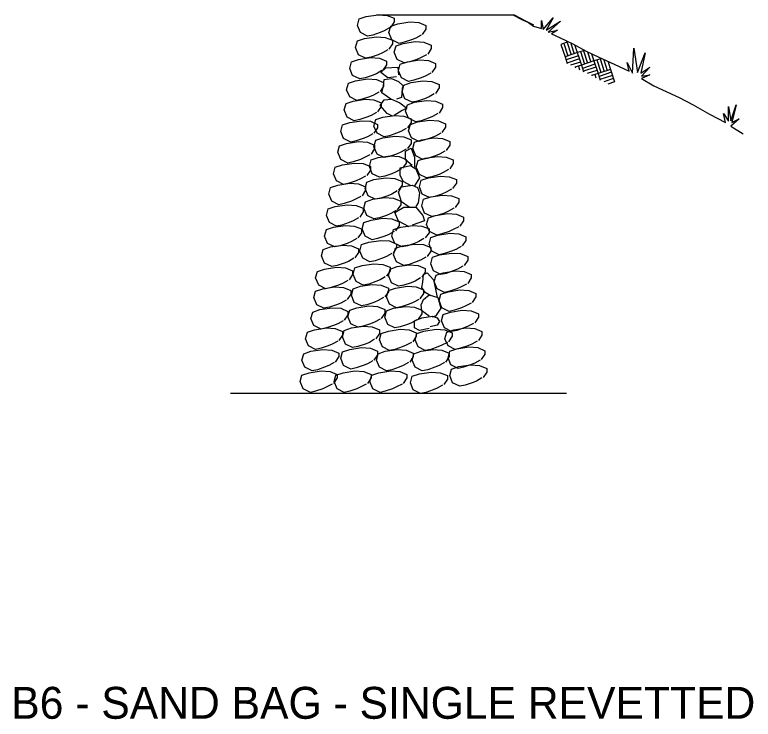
# Model space of a CAD drawing. Extents: x -0.04 to 2.79, y -0.02 to 1.81.
# Drawn here: x 0.1879 to 0.4291, y 0.9318 to 1.1619 of the extents above; entities that cross this region are included whole.
import ezdxf

# ---------------------------------------------------------------- set-up
doc = ezdxf.new("R2010")
doc.units = 0
doc.layers.add('Level 1', color=7, linetype='Continuous')

msp = doc.modelspace()

# ---------------------------------------------------------------- linework, layer by layer
at = {"layer": 'Level 1'}
for p, q in [((0.30607, 1.16192), (0.35105, 1.16192)), ((0.36861, 1.15304), (0.36629, 1.15222)), ((0.36629, 1.15222), (0.36766, 1.14818)), ((0.36731, 1.15256), (0.36861, 1.14853)), ((0.36834, 1.1529), (0.36964, 1.14887)), ((0.36957, 1.15256), (0.37066, 1.14921)), ((0.37087, 1.15187), (0.37306, 1.14545)), ((0.37169, 1.14955), (0.36766, 1.14818)), ((0.37203, 1.14853), (0.368, 1.14716)), ((0.37401, 1.1503), (0.37169, 1.14955)), ((0.37271, 1.14989), (0.37401, 1.14579)), ((0.37374, 1.15017), (0.37504, 1.14613)), ((0.37497, 1.14982), (0.37606, 1.14647)), ((0.37627, 1.14914), (0.37709, 1.14682)), ((0.36766, 1.14818), (0.36834, 1.146)), ((0.37237, 1.1475), (0.36827, 1.14613)), ((0.37271, 1.14647), (0.3695, 1.14545)), ((0.37709, 1.14682), (0.37306, 1.14545)), ((0.37941, 1.14757), (0.37709, 1.14682)), ((0.37709, 1.14682), (0.37846, 1.14278)), ((0.37811, 1.14716), (0.37941, 1.14313)), ((0.37914, 1.1475), (0.38044, 1.1434)), ((0.38037, 1.14716), (0.38146, 1.14374)), ((0.38174, 1.14647), (0.38249, 1.14408)), ((0.37306, 1.14545), (0.37087, 1.14477)), ((0.37306, 1.14545), (0.37087, 1.14477)), ((0.37101, 1.14477), (0.37107, 1.14463)), ((0.37203, 1.14511), (0.37237, 1.14395)), ((0.37306, 1.14545), (0.37374, 1.14326)), ((0.37743, 1.14579), (0.3734, 1.14442)), ((0.37777, 1.14477), (0.37367, 1.14347)), ((0.37811, 1.14374), (0.3749, 1.14272)), ((0.38249, 1.14408), (0.37846, 1.14278)), ((0.38249, 1.14408), (0.38386, 1.14005)), ((0.37846, 1.14278), (0.37627, 1.14203)), ((0.37846, 1.14278), (0.37627, 1.14203)), ((0.37641, 1.1421), (0.37647, 1.14196)), ((0.37743, 1.14244), (0.37777, 1.14128)), ((0.37846, 1.14278), (0.37914, 1.1406)), ((0.38283, 1.14313), (0.3788, 1.14176)), ((0.38317, 1.1421), (0.37907, 1.14073)), ((0.38351, 1.14107), (0.3803, 1.13998)), ((0.38386, 1.14005), (0.38167, 1.1393)), ((0.25836, 1.03828), (0.36814, 1.03828))]:
    msp.add_line(p, q, dxfattribs=at)
for points in [[(0.31031, 1.15762), (0.3086, 1.15666), (0.30723, 1.15611), (0.30491, 1.15529), (0.30313, 1.15495), (0.30081, 1.15611), (0.29985, 1.15844), (0.3004, 1.16055), (0.30272, 1.16131), (0.30662, 1.16192), (0.30956, 1.16172), (0.31188, 1.16076), (0.31188, 1.1596), (0.31072, 1.15782)], [(0.35064, 1.16192), (0.35358, 1.16035), (0.3557, 1.15939), (0.3574, 1.15823), (0.35993, 1.15748), (0.35993, 1.16001), (0.36055, 1.15707), (0.36383, 1.16096), (0.36151, 1.15686), (0.36622, 1.1598), (0.36212, 1.15625), (0.3652, 1.15686), (0.36328, 1.1557), (0.36581, 1.15454), (0.37025, 1.15242), (0.37456, 1.15003), (0.37866, 1.14811), (0.38372, 1.14579), (0.38857, 1.14347), (0.38796, 1.14634), (0.38973, 1.14285), (0.39014, 1.15105), (0.39131, 1.14306), (0.39383, 1.14948), (0.39247, 1.14285), (0.39534, 1.14483), (0.39267, 1.14189), (0.39534, 1.14231), (0.39267, 1.14114), (0.39671, 1.13875), (0.40491, 1.13485), (0.40956, 1.13253), (0.41482, 1.12946), (0.42008, 1.12672), (0.41947, 1.12966), (0.42104, 1.12713), (0.42104, 1.13198), (0.42179, 1.12727), (0.42357, 1.13253), (0.4222, 1.12672), (0.42452, 1.12788), (0.42179, 1.12556), (0.42589, 1.12303)], [(0.35105, 1.16192), (0.35453, 1.16001), (0.3574, 1.15864)], [(0.32063, 1.15529), (0.31892, 1.15433), (0.31756, 1.15372), (0.31516, 1.15297), (0.31345, 1.15256), (0.31113, 1.15372), (0.31011, 1.15611), (0.31072, 1.15823), (0.31304, 1.15898), (0.31694, 1.1596), (0.31988, 1.15939), (0.3222, 1.15844), (0.3222, 1.15727), (0.32104, 1.1555)], [(0.30976, 1.15044), (0.30799, 1.14948), (0.30662, 1.14887), (0.3043, 1.14811), (0.30252, 1.1477), (0.30019, 1.14887), (0.29924, 1.15119), (0.29985, 1.15338), (0.30218, 1.15413), (0.30607, 1.15474), (0.30894, 1.15454), (0.31134, 1.15358), (0.31134, 1.15242), (0.31011, 1.15064)], [(0.32241, 1.14887), (0.32063, 1.14791), (0.31926, 1.14736), (0.31694, 1.14654), (0.31516, 1.1462), (0.31284, 1.14736), (0.31188, 1.14969), (0.3125, 1.15181), (0.31482, 1.15256), (0.31872, 1.15317), (0.32159, 1.15297), (0.32398, 1.15201), (0.32398, 1.15085), (0.32282, 1.14907)], [(0.30778, 1.14367), (0.30607, 1.14265), (0.30471, 1.1421), (0.30238, 1.14128), (0.3006, 1.14094), (0.29828, 1.1421), (0.29732, 1.14442), (0.29787, 1.14654), (0.30019, 1.14736), (0.30409, 1.14791), (0.30703, 1.1477), (0.30935, 1.14675), (0.30935, 1.14559), (0.30819, 1.14381)], [(0.32378, 1.14285), (0.322, 1.14189), (0.32063, 1.14128), (0.31831, 1.14053), (0.31653, 1.14012), (0.31421, 1.14128), (0.31325, 1.1436), (0.31386, 1.14579), (0.31619, 1.14654), (0.32008, 1.14716), (0.32302, 1.14695), (0.32535, 1.146), (0.32535, 1.14483), (0.32419, 1.14306)], [(0.31263, 1.14169), (0.30976, 1.14128), (0.30744, 1.14306), (0.30915, 1.14463), (0.31304, 1.14483), (0.31325, 1.14231)], [(0.31072, 1.13431), (0.30778, 1.13643), (0.3084, 1.13875), (0.3086, 1.14073), (0.31093, 1.14114), (0.31325, 1.14012), (0.31482, 1.13875), (0.31441, 1.13779), (0.31421, 1.13485), (0.31263, 1.13431)], [(0.30682, 1.13663), (0.30505, 1.13568), (0.30375, 1.13506), (0.30136, 1.13431), (0.29965, 1.1339), (0.29732, 1.13506), (0.2963, 1.13738), (0.29691, 1.13957), (0.29924, 1.14032), (0.30313, 1.14094), (0.30607, 1.14073), (0.3084, 1.13978), (0.3084, 1.13861), (0.30723, 1.13684)], [(0.32494, 1.13609), (0.32323, 1.13506), (0.32179, 1.13451), (0.31947, 1.13369), (0.31769, 1.13335), (0.31537, 1.13451), (0.31441, 1.13684), (0.31503, 1.13896), (0.31735, 1.13978), (0.32125, 1.14032), (0.32419, 1.14012), (0.32651, 1.13916), (0.32651, 1.138), (0.32535, 1.13622)], [(0.30607, 1.13), (0.3043, 1.12905), (0.30293, 1.1285), (0.3006, 1.12768), (0.29883, 1.12727), (0.2965, 1.1285), (0.29555, 1.13082), (0.29616, 1.13294), (0.29849, 1.13369), (0.30238, 1.13431), (0.30525, 1.1341), (0.30758, 1.13315), (0.30758, 1.13198), (0.30641, 1.13021)], [(0.31134, 1.12884), (0.30956, 1.12966), (0.30723, 1.13233), (0.3086, 1.1341), (0.31093, 1.13431), (0.31366, 1.13315), (0.31598, 1.13137), (0.31441, 1.13062), (0.31188, 1.12905)], [(0.3261, 1.12966), (0.32439, 1.12863), (0.32302, 1.12809), (0.32063, 1.12727), (0.31892, 1.12693), (0.31653, 1.12809), (0.31557, 1.13041), (0.31619, 1.13253), (0.31851, 1.13335), (0.32241, 1.1339), (0.32535, 1.13369), (0.32767, 1.13274), (0.32767, 1.13157), (0.32651, 1.1298)], [(0.31578, 1.12474), (0.314, 1.12378), (0.31263, 1.12324), (0.31031, 1.12242), (0.3086, 1.12207), (0.30628, 1.12324), (0.30525, 1.12556), (0.30587, 1.12768), (0.30819, 1.1285), (0.31209, 1.12905), (0.31503, 1.12884), (0.31735, 1.12788), (0.31735, 1.12672), (0.31619, 1.12494)], [(0.30491, 1.12303), (0.30313, 1.12207), (0.30177, 1.12146), (0.29944, 1.12071), (0.29767, 1.1203), (0.29534, 1.12146), (0.29438, 1.12378), (0.29493, 1.12597), (0.29732, 1.12672), (0.30122, 1.12727), (0.30409, 1.12713), (0.30641, 1.12611), (0.30641, 1.12494), (0.30525, 1.12324)], [(0.32712, 1.12324), (0.32535, 1.12221), (0.32398, 1.12166), (0.32159, 1.12091), (0.31988, 1.1205), (0.31756, 1.12166), (0.31653, 1.12399), (0.31715, 1.12611), (0.31947, 1.12693), (0.32337, 1.12747), (0.3263, 1.12727), (0.32863, 1.12631), (0.32863, 1.12515), (0.32747, 1.12344)], [(0.32712, 1.12324), (0.32535, 1.12221), (0.32398, 1.12166), (0.32159, 1.12091), (0.31988, 1.1205), (0.31756, 1.12166), (0.31653, 1.12399), (0.31715, 1.12611), (0.31947, 1.12693), (0.32337, 1.12747), (0.3263, 1.12727), (0.32863, 1.12631), (0.32863, 1.12515), (0.32747, 1.12344)], [(0.31578, 1.11797), (0.314, 1.11702), (0.31263, 1.1164), (0.31031, 1.11565), (0.3086, 1.11524), (0.30628, 1.1164), (0.30525, 1.11872), (0.30587, 1.12091), (0.30819, 1.12166), (0.31209, 1.12221), (0.31503, 1.12207), (0.31735, 1.12105), (0.31735, 1.11989), (0.31619, 1.11818)], [(0.30389, 1.1162), (0.30218, 1.11524), (0.30081, 1.11462), (0.29849, 1.11387), (0.29671, 1.11346), (0.29438, 1.11462), (0.29343, 1.11702), (0.29397, 1.11913), (0.2963, 1.11989), (0.30019, 1.1205), (0.30313, 1.1203), (0.30546, 1.11934), (0.30546, 1.11818), (0.3043, 1.1164)], [(0.32842, 1.11736), (0.32671, 1.1164), (0.32535, 1.11585), (0.32302, 1.11503), (0.32125, 1.11462), (0.31892, 1.11585), (0.3179, 1.11818), (0.31851, 1.1203), (0.32084, 1.12105), (0.32473, 1.12166), (0.32767, 1.12146), (0.33, 1.1205), (0.33, 1.11934), (0.32883, 1.11756)], [(0.31769, 1.11271), (0.31557, 1.11449), (0.31557, 1.11736), (0.31735, 1.11838), (0.31851, 1.11544), (0.31851, 1.11209)], [(0.31421, 1.11155), (0.3125, 1.11059), (0.31113, 1.10998), (0.30881, 1.10922), (0.30703, 1.10881), (0.30471, 1.10998), (0.30375, 1.1123), (0.3043, 1.11449), (0.30662, 1.11524), (0.31052, 1.11585), (0.31345, 1.11565), (0.31578, 1.11462), (0.31578, 1.11346), (0.31462, 1.11175)], [(0.32965, 1.11134), (0.32788, 1.11039), (0.32651, 1.10977), (0.32419, 1.10902), (0.32241, 1.10861), (0.32008, 1.10977), (0.31906, 1.11209), (0.31967, 1.11428), (0.322, 1.11503), (0.32589, 1.11565), (0.32883, 1.11544), (0.33116, 1.11449), (0.33116, 1.11332), (0.33, 1.11155)], [(0.30252, 1.10922), (0.30081, 1.10827), (0.29944, 1.10765), (0.29712, 1.1069), (0.29534, 1.10649), (0.29302, 1.10765), (0.29206, 1.10998), (0.29261, 1.11209), (0.29493, 1.11291), (0.29883, 1.11346), (0.30177, 1.11332), (0.30409, 1.1123), (0.30409, 1.11114), (0.30293, 1.10943)], [(0.31735, 1.10608), (0.31482, 1.10745), (0.31386, 1.10957), (0.31386, 1.11196), (0.31715, 1.11271), (0.31892, 1.11155), (0.32008, 1.10861), (0.31851, 1.10608)], [(0.31284, 1.10437), (0.31113, 1.10335), (0.30976, 1.1028), (0.30744, 1.10205), (0.30566, 1.10164), (0.30334, 1.1028), (0.30238, 1.10512), (0.30293, 1.10724), (0.30525, 1.10806), (0.30915, 1.10861), (0.31209, 1.1084), (0.31441, 1.10745), (0.31441, 1.10628), (0.31325, 1.10458)], [(0.33061, 1.10492), (0.32883, 1.10396), (0.32747, 1.10335), (0.32514, 1.10259), (0.32337, 1.10218), (0.32104, 1.10335), (0.32008, 1.10574), (0.32063, 1.10786), (0.32302, 1.10861), (0.32692, 1.10922), (0.32979, 1.10902), (0.33218, 1.10806), (0.33218, 1.1069), (0.33095, 1.10512)], [(0.30101, 1.10259), (0.29924, 1.10164), (0.29787, 1.10102), (0.29555, 1.10027), (0.29377, 1.09986), (0.29145, 1.10102), (0.29049, 1.10335), (0.2911, 1.10553), (0.29343, 1.10628), (0.29732, 1.1069), (0.30019, 1.10669), (0.30252, 1.10574), (0.30252, 1.10458), (0.30136, 1.1028)], [(0.31674, 1.09911), (0.31421, 1.10082), (0.31325, 1.10396), (0.31421, 1.10574), (0.31769, 1.10628), (0.31947, 1.10553), (0.32008, 1.10376), (0.31967, 1.10047), (0.31892, 1.09931)], [(0.33136, 1.0987), (0.32965, 1.09774), (0.32829, 1.09713), (0.32589, 1.09637), (0.32419, 1.09596), (0.32179, 1.09713), (0.32084, 1.09952), (0.32145, 1.10164), (0.32378, 1.10239), (0.32767, 1.103), (0.33061, 1.1028), (0.33293, 1.10184), (0.33293, 1.10068), (0.33177, 1.0989)], [(0.3125, 1.09795), (0.31072, 1.09699), (0.30935, 1.09637), (0.30703, 1.09562), (0.30525, 1.09521), (0.30293, 1.09637), (0.30197, 1.0987), (0.30252, 1.10082), (0.30491, 1.10164), (0.30881, 1.10218), (0.31168, 1.10205), (0.314, 1.10102), (0.314, 1.09986), (0.31284, 1.09815)], [(0.30019, 1.09562), (0.29849, 1.0946), (0.29712, 1.09405), (0.29479, 1.09323), (0.29302, 1.09289), (0.29069, 1.09405), (0.28974, 1.09637), (0.29028, 1.09849), (0.29261, 1.09931), (0.2965, 1.09986), (0.29944, 1.09965), (0.30177, 1.0987), (0.30177, 1.09754), (0.3006, 1.09576)], [(0.31674, 1.09268), (0.31325, 1.09446), (0.31209, 1.09733), (0.31503, 1.09911), (0.31892, 1.09911), (0.32125, 1.09637), (0.32179, 1.0946), (0.31769, 1.09323)], [(0.31188, 1.09111), (0.31011, 1.09015), (0.30881, 1.08954), (0.30641, 1.08879), (0.30471, 1.08838), (0.30238, 1.08954), (0.30136, 1.09193), (0.30197, 1.09405), (0.3043, 1.0948), (0.30819, 1.09542), (0.31113, 1.09521), (0.31345, 1.09425), (0.31345, 1.09309), (0.31229, 1.09132)], [(0.33293, 1.09268), (0.33116, 1.09173), (0.32979, 1.09111), (0.32747, 1.09036), (0.32576, 1.08995), (0.32337, 1.09111), (0.32241, 1.09343), (0.32302, 1.09562), (0.32535, 1.09637), (0.32924, 1.09699), (0.33218, 1.09678), (0.33451, 1.09576), (0.33451, 1.0946), (0.33334, 1.09289)], [(0.29965, 1.08879), (0.29787, 1.08783), (0.2965, 1.08721), (0.29418, 1.08646), (0.29247, 1.08605), (0.29008, 1.08721), (0.28912, 1.08954), (0.28974, 1.09173), (0.29206, 1.09248), (0.29596, 1.09309), (0.29883, 1.09289), (0.30122, 1.09193), (0.30122, 1.0907), (0.29999, 1.08899)], [(0.32159, 1.08879), (0.31988, 1.08783), (0.31851, 1.08721), (0.31619, 1.08646), (0.31441, 1.08605), (0.31209, 1.08721), (0.31113, 1.08954), (0.31168, 1.09173), (0.314, 1.09248), (0.3179, 1.09309), (0.32084, 1.09289), (0.32323, 1.09193), (0.32323, 1.0907), (0.322, 1.08899)], [(0.33369, 1.08626), (0.33198, 1.08523), (0.33061, 1.08469), (0.32829, 1.08387), (0.32651, 1.08352), (0.32419, 1.08469), (0.32323, 1.08701), (0.32378, 1.0892), (0.3261, 1.08995), (0.33, 1.09056), (0.33293, 1.09036), (0.33526, 1.0894), (0.33526, 1.08817), (0.3341, 1.08646)], [(0.31113, 1.08387), (0.30935, 1.08291), (0.30799, 1.08236), (0.30566, 1.08154), (0.30389, 1.0812), (0.30156, 1.08236), (0.3006, 1.08469), (0.30122, 1.08687), (0.30354, 1.08762), (0.30744, 1.08817), (0.31031, 1.08803), (0.31263, 1.08701), (0.31263, 1.08585), (0.31147, 1.08407)], [(0.29869, 1.08236), (0.29691, 1.08134), (0.29555, 1.08079), (0.29322, 1.07997), (0.29145, 1.07963), (0.28912, 1.08079), (0.28816, 1.08311), (0.28871, 1.08523), (0.2911, 1.08605), (0.29493, 1.08667), (0.29787, 1.08646), (0.30019, 1.08544), (0.30019, 1.08428), (0.29903, 1.0825)], [(0.3222, 1.0827), (0.32043, 1.08175), (0.31906, 1.0812), (0.31674, 1.08038), (0.31503, 1.07997), (0.31263, 1.0812), (0.31168, 1.08352), (0.31229, 1.08564), (0.31462, 1.08646), (0.31851, 1.08701), (0.32145, 1.08687), (0.32378, 1.08585), (0.32378, 1.08469), (0.32261, 1.08291)], [(0.3343, 1.07983), (0.33252, 1.07881), (0.33116, 1.07826), (0.32883, 1.07744), (0.32712, 1.0771), (0.32473, 1.07826), (0.32378, 1.08058), (0.32439, 1.0827), (0.32671, 1.08352), (0.33061, 1.08407), (0.33348, 1.08387), (0.33587, 1.08291), (0.33587, 1.08175), (0.33471, 1.07997)], [(0.29671, 1.07512), (0.29493, 1.07416), (0.29363, 1.07361), (0.29124, 1.07279), (0.28953, 1.07238), (0.28721, 1.07361), (0.28618, 1.07594), (0.2868, 1.07806), (0.28912, 1.07881), (0.29302, 1.07942), (0.29596, 1.07922), (0.29828, 1.07826), (0.29828, 1.0771), (0.29712, 1.07532)], [(0.30894, 1.07628), (0.30723, 1.07532), (0.30587, 1.07477), (0.30354, 1.07395), (0.30177, 1.07361), (0.29944, 1.07477), (0.29849, 1.0771), (0.29903, 1.07922), (0.30136, 1.07997), (0.30525, 1.08058), (0.30819, 1.08038), (0.31052, 1.07942), (0.31052, 1.07826), (0.30935, 1.07648)], [(0.32043, 1.07594), (0.31872, 1.07491), (0.31735, 1.07436), (0.31503, 1.07361), (0.31325, 1.0732), (0.31093, 1.07436), (0.30997, 1.07669), (0.31052, 1.07881), (0.31284, 1.07963), (0.31674, 1.08017), (0.31967, 1.07997), (0.322, 1.07901), (0.322, 1.07785), (0.32084, 1.07614)], [(0.32378, 1.07006), (0.322, 1.07122), (0.32084, 1.07279), (0.32125, 1.07457), (0.32145, 1.0771), (0.32261, 1.07765), (0.32473, 1.07532), (0.32535, 1.07225), (0.32589, 1.06951)], [(0.33546, 1.07395), (0.33369, 1.073), (0.33232, 1.07238), (0.33, 1.07163), (0.32829, 1.07122), (0.32589, 1.07238), (0.32494, 1.07477), (0.32555, 1.07689), (0.32788, 1.07765), (0.33177, 1.07826), (0.33471, 1.07806), (0.33704, 1.0771), (0.33704, 1.07594), (0.33587, 1.07416)], [(0.3084, 1.06951), (0.30662, 1.06855), (0.30525, 1.06794), (0.30293, 1.06719), (0.30122, 1.06678), (0.29883, 1.06794), (0.29787, 1.07026), (0.29849, 1.07238), (0.30081, 1.0732), (0.30471, 1.07375), (0.30758, 1.07361), (0.30997, 1.07259), (0.30997, 1.07143), (0.30881, 1.06972)], [(0.29616, 1.06869), (0.29438, 1.06773), (0.29302, 1.06719), (0.29069, 1.06637), (0.28892, 1.06603), (0.28659, 1.06719), (0.28564, 1.06951), (0.28618, 1.07163), (0.28857, 1.07238), (0.2924, 1.073), (0.29534, 1.07279), (0.29767, 1.07184), (0.29767, 1.07067), (0.2965, 1.0689)], [(0.31988, 1.0689), (0.3181, 1.06794), (0.31674, 1.06732), (0.31441, 1.06657), (0.31263, 1.06616), (0.31031, 1.06732), (0.30935, 1.06972), (0.30997, 1.07184), (0.31229, 1.07259), (0.31619, 1.0732), (0.31906, 1.073), (0.32145, 1.07204), (0.32145, 1.07088), (0.32022, 1.0691)], [(0.33704, 1.06773), (0.33526, 1.06678), (0.33389, 1.06616), (0.33157, 1.06541), (0.32979, 1.065), (0.32747, 1.06616), (0.32651, 1.06855), (0.32712, 1.07067), (0.32945, 1.07143), (0.33334, 1.07204), (0.33622, 1.07184), (0.33854, 1.07088), (0.33854, 1.06972), (0.33738, 1.06794)], [(0.32323, 1.0635), (0.32084, 1.06521), (0.32063, 1.06719), (0.32145, 1.0689), (0.32323, 1.07047), (0.3261, 1.06951), (0.32712, 1.06603), (0.32535, 1.0635), (0.32419, 1.06309)], [(0.30723, 1.06247), (0.30546, 1.06151), (0.30409, 1.06097), (0.30177, 1.06015), (0.29999, 1.05981), (0.29767, 1.06097), (0.29671, 1.06329), (0.29732, 1.06541), (0.29965, 1.06616), (0.30354, 1.06678), (0.30641, 1.06657), (0.30881, 1.06562), (0.30881, 1.06445), (0.30758, 1.06268)], [(0.31926, 1.06227), (0.31756, 1.06131), (0.31619, 1.06076), (0.31386, 1.05994), (0.31209, 1.0596), (0.30976, 1.06076), (0.30881, 1.06309), (0.30935, 1.06521), (0.31168, 1.06603), (0.31557, 1.06657), (0.31851, 1.06637), (0.32084, 1.06541), (0.32084, 1.06425), (0.31967, 1.06247)], [(0.29514, 1.06192), (0.29343, 1.06097), (0.29206, 1.06035), (0.28974, 1.0596), (0.28796, 1.05919), (0.28564, 1.06035), (0.28468, 1.06268), (0.28523, 1.0648), (0.28755, 1.06562), (0.29145, 1.06616), (0.29438, 1.06603), (0.29671, 1.065), (0.29671, 1.06384), (0.29555, 1.06213)], [(0.33779, 1.0611), (0.33601, 1.06015), (0.33471, 1.0596), (0.33232, 1.05878), (0.33061, 1.05844), (0.32829, 1.0596), (0.32726, 1.06192), (0.32788, 1.06404), (0.3302, 1.0648), (0.3341, 1.06541), (0.33704, 1.06521), (0.33936, 1.06425), (0.33936, 1.06309), (0.3382, 1.06131)], [(0.32323, 1.0594), (0.32008, 1.05878), (0.31851, 1.0596), (0.31851, 1.06192), (0.32084, 1.06288), (0.32439, 1.0635), (0.32589, 1.06288), (0.32671, 1.06172), (0.32589, 1.06056), (0.32357, 1.05994)], [(0.29343, 1.05529), (0.29165, 1.05434), (0.29028, 1.05372), (0.28796, 1.05297), (0.28618, 1.05256), (0.28386, 1.05372), (0.2829, 1.05605), (0.28352, 1.05823), (0.28584, 1.05899), (0.28974, 1.0596), (0.29261, 1.0594), (0.29493, 1.05844), (0.29493, 1.05721), (0.29377, 1.0555)], [(0.30546, 1.05591), (0.30375, 1.05488), (0.30238, 1.05434), (0.29999, 1.05352), (0.29828, 1.05318), (0.29596, 1.05434), (0.29493, 1.05666), (0.29555, 1.05878), (0.29787, 1.0596), (0.30177, 1.06015), (0.30471, 1.05994), (0.30703, 1.05899), (0.30703, 1.05782), (0.30587, 1.05605)], [(0.31756, 1.05488), (0.31578, 1.05393), (0.31441, 1.05338), (0.31209, 1.05256), (0.31031, 1.05222), (0.30799, 1.05338), (0.30703, 1.0557), (0.30758, 1.05782), (0.30997, 1.05858), (0.31386, 1.05919), (0.31674, 1.05899), (0.31906, 1.05803), (0.31906, 1.05687), (0.3179, 1.05509)], [(0.32924, 1.05488), (0.32747, 1.05393), (0.3261, 1.05338), (0.32378, 1.05256), (0.322, 1.05222), (0.31967, 1.05338), (0.31872, 1.0557), (0.31926, 1.05782), (0.32159, 1.05858), (0.32555, 1.05919), (0.32842, 1.05899), (0.33082, 1.05803), (0.33082, 1.05687), (0.32965, 1.05509)], [(0.33895, 1.05529), (0.33724, 1.05434), (0.33587, 1.05372), (0.33348, 1.05297), (0.33177, 1.05256), (0.32945, 1.05372), (0.32842, 1.05605), (0.32904, 1.05823), (0.33136, 1.05899), (0.33526, 1.0596), (0.3382, 1.0594), (0.34052, 1.05844), (0.34052, 1.05721), (0.33936, 1.0555)], [(0.29227, 1.04832), (0.29049, 1.0473), (0.28912, 1.04675), (0.2868, 1.04593), (0.28502, 1.04559), (0.2827, 1.04675), (0.28174, 1.04907), (0.28235, 1.05119), (0.28468, 1.05201), (0.28857, 1.05256), (0.29145, 1.05236), (0.29377, 1.0514), (0.29377, 1.05024), (0.29261, 1.04846)], [(0.30491, 1.04887), (0.30313, 1.04791), (0.30177, 1.0473), (0.29944, 1.04655), (0.29767, 1.04614), (0.29534, 1.0473), (0.29438, 1.04969), (0.29493, 1.05181), (0.29732, 1.05256), (0.30122, 1.05318), (0.30409, 1.05297), (0.30641, 1.05201), (0.30641, 1.05085), (0.30525, 1.04907)], [(0.31653, 1.04832), (0.31482, 1.0473), (0.31345, 1.04675), (0.31113, 1.04593), (0.30935, 1.04559), (0.30703, 1.04675), (0.30607, 1.04907), (0.30662, 1.05119), (0.30894, 1.05201), (0.31284, 1.05256), (0.31578, 1.05236), (0.3181, 1.0514), (0.3181, 1.05024), (0.31694, 1.04846)], [(0.32829, 1.04832), (0.32651, 1.0473), (0.32514, 1.04675), (0.32282, 1.04593), (0.32104, 1.04559), (0.31872, 1.04675), (0.31769, 1.04907), (0.31831, 1.05119), (0.32063, 1.05201), (0.3246, 1.05256), (0.32747, 1.05236), (0.32979, 1.0514), (0.32979, 1.05024), (0.32863, 1.04846)], [(0.33991, 1.04907), (0.3382, 1.04812), (0.33683, 1.0475), (0.33451, 1.04675), (0.33273, 1.04634), (0.33041, 1.0475), (0.32945, 1.04983), (0.33, 1.05201), (0.33232, 1.05277), (0.33622, 1.05338), (0.33915, 1.05318), (0.34148, 1.05215), (0.34148, 1.05099), (0.34032, 1.04928)], [(0.34052, 1.04326), (0.33874, 1.04224), (0.33738, 1.04169), (0.33505, 1.04087), (0.33334, 1.04053), (0.33095, 1.04169), (0.33, 1.04402), (0.33061, 1.04614), (0.33293, 1.04696), (0.33683, 1.0475), (0.33977, 1.0473), (0.34209, 1.04634), (0.34209, 1.04518), (0.34093, 1.0434)], [(0.29165, 1.04128), (0.28987, 1.04033), (0.28857, 1.03971), (0.28618, 1.03896), (0.28447, 1.03855), (0.28215, 1.03971), (0.28112, 1.0421), (0.28174, 1.04422), (0.28406, 1.04497), (0.28796, 1.04559), (0.2909, 1.04538), (0.29322, 1.04443), (0.29322, 1.04326), (0.29206, 1.04149)], [(0.30272, 1.04128), (0.30101, 1.04033), (0.29965, 1.03971), (0.29732, 1.03896), (0.29555, 1.03855), (0.29322, 1.03971), (0.29227, 1.0421), (0.29281, 1.04422), (0.29514, 1.04497), (0.29903, 1.04559), (0.30197, 1.04538), (0.3043, 1.04443), (0.3043, 1.04326), (0.30313, 1.04149)], [(0.31441, 1.04128), (0.31263, 1.04033), (0.31134, 1.03971), (0.30894, 1.03896), (0.30723, 1.03855), (0.30491, 1.03971), (0.30389, 1.0421), (0.3045, 1.04422), (0.30682, 1.04497), (0.31072, 1.04559), (0.31366, 1.04538), (0.31598, 1.04443), (0.31598, 1.04326), (0.31482, 1.04149)], [(0.32767, 1.04087), (0.32589, 1.03992), (0.3246, 1.03937), (0.3222, 1.03855), (0.32043, 1.03821), (0.3181, 1.03937), (0.31715, 1.04169), (0.31769, 1.04381), (0.32008, 1.04463), (0.32398, 1.04518), (0.32692, 1.04497), (0.32924, 1.04402), (0.32924, 1.04285), (0.32808, 1.04108)]]:
    msp.add_lwpolyline(points, dxfattribs=at)

# ---------------------------------------------------------------- texts
msp.add_text('B6 - SAND BAG - SINGLE REVETTED', height=0.0104167).set_placement((0.18677, 0.93191))

doc.saveas('drawing.dxf')
